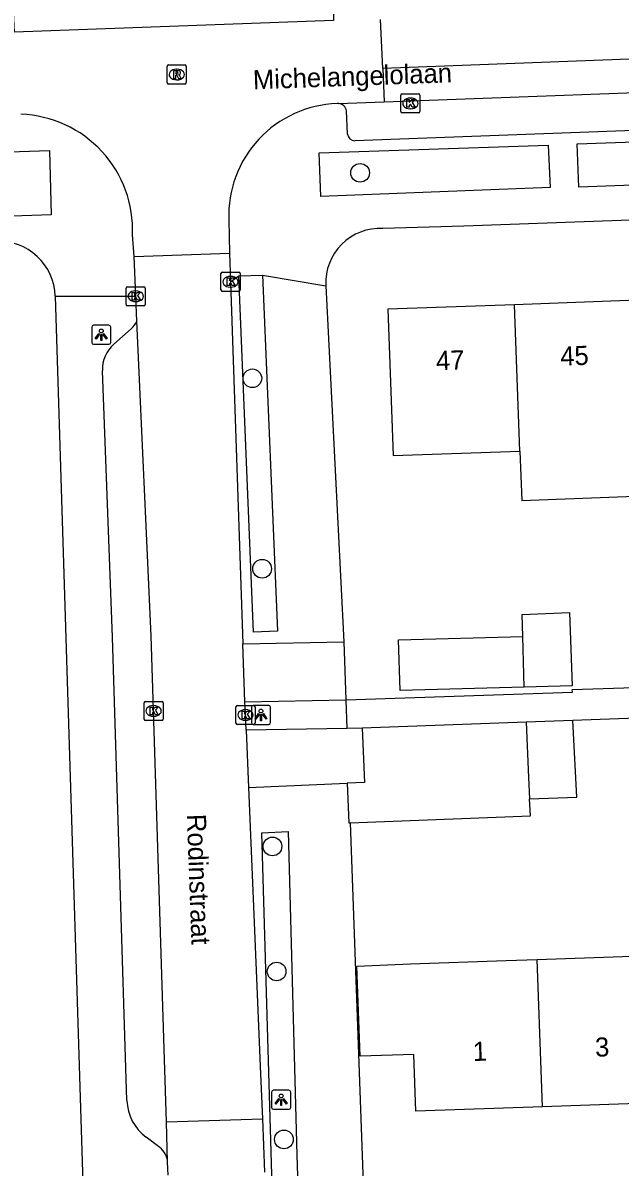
# Model space of a CAD drawing. Extents: x 160557 to 161245, y 385330 to 386505.
# Drawn here: x 160836.9 to 160868.1, y 386095.1 to 386154.9 of the extents above; entities that cross this region are included whole.
import ezdxf

# ---------------------------------------------------------------- set-up
doc = ezdxf.new("R2010")
doc.units = 0
for name, color, linetype in [('IMGEO_Boom', 7, 'Continuous'), ('IMGEO_Kolk', 7, 'Continuous'), ('IMGEO_Lichtpunt', 7, 'Continuous'), ('IMGEO_Openbare_ruimte_label', 7, 'Continuous'), ('IMGEO_Pand', 7, 'Continuous'), ('IMGEO_Pand_nummerreeks', 7, 'Continuous'), ('IMGEO_Rijbaan_lokaal_gesloten', 7, 'Continuous'), ('IMGEO_Rijbaan_lokaal_open', 7, 'Continuous'), ('IMGEO_Rioolput', 7, 'Continuous'), ('IMGEO_Voetpad_open', 7, 'Continuous')]:
    doc.layers.add(name, color=color, linetype=linetype)

msp = doc.modelspace()

# ---------------------------------------------------------------- linework, layer by layer
at = {"layer": 'IMGEO_Boom'}
for centre in [(160854.55, 386147.084), (160848.92, 386136.333), (160849.431, 386126.371), (160849.969, 386111.841), (160850.188, 386105.298), (160850.569, 386096.513)]:
    msp.add_circle(centre, 0.489, dxfattribs=at)
at = {"layer": 'IMGEO_Kolk'}
for p, q in [((160856.679, 386150.291), (160856.679, 386151.143)), ((160856.754, 386151.217), (160857.606, 386151.217)), ((160857.167, 386150.997), (160857.192, 386150.997)), ((160857.68, 386151.143), (160857.68, 386150.291)), ((160857.606, 386150.217), (160856.754, 386150.217)), ((160857.19, 386150.437), (160857.165, 386150.437)), ((160847.277, 386140.957), (160847.277, 386141.809)), ((160847.352, 386141.883), (160848.204, 386141.883)), ((160848.278, 386141.809), (160848.278, 386140.957)), ((160842.397, 386141.124), (160843.249, 386141.124)), ((160847.788, 386141.103), (160847.763, 386141.103)), ((160847.765, 386141.663), (160847.79, 386141.663)), ((160842.322, 386140.198), (160842.322, 386141.05)), ((160842.81, 386140.904), (160842.835, 386140.904)), ((160843.323, 386141.05), (160843.323, 386140.198)), ((160848.204, 386140.883), (160847.352, 386140.883)), ((160843.249, 386140.124), (160842.397, 386140.124)), ((160842.833, 386140.344), (160842.808, 386140.344)), ((160843.258, 386118.504), (160843.258, 386119.356)), ((160843.333, 386119.43), (160844.185, 386119.43)), ((160843.746, 386119.21), (160843.771, 386119.21)), ((160844.259, 386119.356), (160844.259, 386118.504)), ((160848.06, 386118.293), (160848.06, 386119.145)), ((160848.135, 386119.219), (160848.987, 386119.219)), ((160848.548, 386118.999), (160848.573, 386118.999)), ((160849.061, 386119.145), (160849.061, 386118.293)), ((160844.185, 386118.43), (160843.333, 386118.43)), ((160843.769, 386118.65), (160843.744, 386118.65)), ((160848.571, 386118.439), (160848.546, 386118.439)), ((160848.987, 386118.219), (160848.135, 386118.219))]:
    msp.add_line(p, q, dxfattribs=at)
for points in [[(160856.679, 386150.291), (160856.679, 386151.143)], [(160856.754, 386151.217), (160857.606, 386151.217)], [(160857, 386150.917), (160857.123, 386150.917), (160857.123, 386150.766), (160857.253, 386150.917), (160857.417, 386150.917), (160857.271, 386150.766), (160857.424, 386150.517), (160857.272, 386150.517), (160857.187, 386150.681), (160857.123, 386150.614), (160857.123, 386150.517), (160857, 386150.517), (160857, 386150.917)], [(160857.68, 386151.143), (160857.68, 386150.291)], [(160857.606, 386150.217), (160856.754, 386150.217)], [(160847.277, 386140.957), (160847.277, 386141.809)], [(160847.352, 386141.883), (160848.204, 386141.883)], [(160848.278, 386141.809), (160848.278, 386140.957)], [(160842.397, 386141.124), (160843.249, 386141.124)], [(160847.598, 386141.583), (160847.721, 386141.583), (160847.721, 386141.432), (160847.851, 386141.583), (160848.015, 386141.583), (160847.869, 386141.432), (160848.022, 386141.183), (160847.87, 386141.183), (160847.785, 386141.347), (160847.721, 386141.28), (160847.721, 386141.183), (160847.598, 386141.183), (160847.598, 386141.583)], [(160842.322, 386140.198), (160842.322, 386141.05)], [(160842.643, 386140.824), (160842.766, 386140.824), (160842.766, 386140.673), (160842.896, 386140.824), (160843.06, 386140.824), (160842.914, 386140.673), (160843.067, 386140.424), (160842.915, 386140.424), (160842.83, 386140.588), (160842.766, 386140.521), (160842.766, 386140.424), (160842.643, 386140.424), (160842.643, 386140.824)], [(160843.323, 386141.05), (160843.323, 386140.198)], [(160848.204, 386140.883), (160847.352, 386140.883)], [(160843.249, 386140.124), (160842.397, 386140.124)], [(160843.258, 386118.504), (160843.258, 386119.356)], [(160843.333, 386119.43), (160844.185, 386119.43)], [(160843.579, 386119.13), (160843.702, 386119.13), (160843.702, 386118.979), (160843.832, 386119.13), (160843.996, 386119.13), (160843.85, 386118.979), (160844.003, 386118.73), (160843.851, 386118.73), (160843.766, 386118.894), (160843.702, 386118.827), (160843.702, 386118.73), (160843.579, 386118.73), (160843.579, 386119.13)], [(160844.259, 386119.356), (160844.259, 386118.504)], [(160848.06, 386118.293), (160848.06, 386119.145)], [(160848.135, 386119.219), (160848.987, 386119.219)], [(160849.061, 386119.145), (160849.061, 386118.293)], [(160844.185, 386118.43), (160843.333, 386118.43)], [(160848.381, 386118.919), (160848.504, 386118.919), (160848.504, 386118.768), (160848.634, 386118.919), (160848.798, 386118.919), (160848.652, 386118.768), (160848.805, 386118.519), (160848.653, 386118.519), (160848.568, 386118.683), (160848.504, 386118.616), (160848.504, 386118.519), (160848.381, 386118.519), (160848.381, 386118.919)], [(160848.987, 386118.219), (160848.135, 386118.219)]]:
    msp.add_lwpolyline(points, dxfattribs=at)
for centre, start, end in [((160856.756, 386151.141), 91.55205, 178.44795), ((160856.756, 386151.141), 91.55205, 178.44795), ((160857.604, 386151.141), 1.55205, 88.44795), ((160857.604, 386151.141), 1.55205, 88.44795), ((160856.756, 386150.293), 181.55205, 268.44795), ((160856.756, 386150.293), 181.55205, 268.44795), ((160857.604, 386150.293), 271.55205, 358.44795), ((160857.604, 386150.293), 271.55205, 358.44795), ((160847.354, 386141.807), 91.55205, 178.44795), ((160847.354, 386141.807), 91.55205, 178.44795), ((160848.202, 386141.807), 1.55205, 88.44795), ((160848.202, 386141.807), 1.55205, 88.44795), ((160842.399, 386141.048), 91.55205, 178.44795), ((160842.399, 386141.048), 91.55205, 178.44795), ((160843.247, 386141.048), 1.55205, 88.44795), ((160843.247, 386141.048), 1.55205, 88.44795), ((160847.354, 386140.959), 181.55205, 268.44795), ((160847.354, 386140.959), 181.55205, 268.44795), ((160848.202, 386140.959), 271.55205, 358.44795), ((160848.202, 386140.959), 271.55205, 358.44795), ((160842.399, 386140.2), 181.55205, 268.44795), ((160842.399, 386140.2), 181.55205, 268.44795), ((160843.247, 386140.2), 271.55205, 358.44795), ((160843.247, 386140.2), 271.55205, 358.44795), ((160843.335, 386119.354), 91.55205, 178.44795), ((160843.335, 386119.354), 91.55205, 178.44795), ((160844.183, 386119.354), 1.55205, 88.44795), ((160844.183, 386119.354), 1.55205, 88.44795), ((160848.137, 386119.143), 91.55205, 178.44795), ((160848.137, 386119.143), 91.55205, 178.44795), ((160848.985, 386119.143), 1.55205, 88.44795), ((160848.985, 386119.143), 1.55205, 88.44795), ((160843.335, 386118.506), 181.55205, 268.44795), ((160843.335, 386118.506), 181.55205, 268.44795), ((160844.183, 386118.506), 271.55205, 358.44795), ((160844.183, 386118.506), 271.55205, 358.44795), ((160848.137, 386118.295), 181.55205, 268.44795), ((160848.137, 386118.295), 181.55205, 268.44795), ((160848.985, 386118.295), 271.55205, 358.44795), ((160848.985, 386118.295), 271.55205, 358.44795)]:
    msp.add_arc(centre, 0.0765, start, end, dxfattribs=at)
for centre, major_axis, ratio, start_param, end_param in [((160857.166, 386150.717), (-0.387, 0.002), 0.722429, 4.712389, 7.853982), ((160857.191, 386150.717), (-0.39, 0.002), 0.717154, 1.570796, 4.712389), ((160847.764, 386141.383), (-0.387, 0.002), 0.722429, 4.712389, 7.853982), ((160847.789, 386141.383), (-0.39, 0.002), 0.717154, 1.570796, 4.712389), ((160842.809, 386140.624), (-0.387, 0.002), 0.722429, 4.712389, 7.853982), ((160842.834, 386140.624), (-0.39, 0.002), 0.717154, 1.570796, 4.712389), ((160843.745, 386118.93), (-0.387, 0.002), 0.722429, 4.712389, 7.853982), ((160843.77, 386118.93), (-0.39, 0.002), 0.717154, 1.570796, 4.712389), ((160848.547, 386118.719), (-0.387, 0.002), 0.722429, 4.712389, 7.853982), ((160848.572, 386118.719), (-0.39, 0.002), 0.717154, 1.570796, 4.712389)]:
    msp.add_ellipse(centre, major_axis=major_axis, ratio=ratio, start_param=start_param, end_param=end_param, dxfattribs=at)
at = {"layer": 'IMGEO_Lichtpunt'}
for p, q in [((160840.524, 386139.014), (160840.524, 386138.207)), ((160840.524, 386139.014), (160840.524, 386138.207)), ((160841.426, 386139.109), (160840.618, 386139.109)), ((160841.426, 386139.109), (160840.618, 386139.109)), ((160841.52, 386138.207), (160841.52, 386139.014)), ((160841.52, 386138.207), (160841.52, 386139.014)), ((160840.618, 386138.113), (160841.426, 386138.113)), ((160840.618, 386138.113), (160841.426, 386138.113)), ((160848.871, 386119.125), (160848.871, 386118.318)), ((160848.871, 386119.125), (160848.871, 386118.318)), ((160849.773, 386119.22), (160848.965, 386119.22)), ((160849.773, 386119.22), (160848.965, 386119.22)), ((160849.867, 386118.318), (160849.867, 386119.125)), ((160849.867, 386118.318), (160849.867, 386119.125)), ((160848.965, 386118.224), (160849.773, 386118.224)), ((160848.965, 386118.224), (160849.773, 386118.224)), ((160849.928, 386098.99), (160849.928, 386098.183)), ((160849.928, 386098.99), (160849.928, 386098.183)), ((160850.83, 386099.085), (160850.022, 386099.085)), ((160850.83, 386099.085), (160850.022, 386099.085)), ((160850.924, 386098.183), (160850.924, 386098.99)), ((160850.924, 386098.183), (160850.924, 386098.99)), ((160850.022, 386098.089), (160850.83, 386098.089)), ((160850.022, 386098.089), (160850.83, 386098.089))]:
    msp.add_line(p, q, dxfattribs=at)
for points in [[(160840.898, 386138.678), (160840.937, 386138.65), (160840.749, 386138.388), (160840.711, 386138.415), (160840.898, 386138.678)], [(160841, 386138.63), (160841.047, 386138.63), (160841.047, 386138.308), (160841, 386138.308), (160841, 386138.63)], [(160841.11, 386138.65), (160841.148, 386138.677), (160841.335, 386138.415), (160841.296, 386138.387), (160841.11, 386138.65)], [(160849.245, 386118.789), (160849.284, 386118.761), (160849.096, 386118.499), (160849.058, 386118.526), (160849.245, 386118.789)], [(160849.347, 386118.741), (160849.394, 386118.741), (160849.394, 386118.419), (160849.347, 386118.419), (160849.347, 386118.741)], [(160849.457, 386118.761), (160849.495, 386118.788), (160849.682, 386118.526), (160849.643, 386118.498), (160849.457, 386118.761)], [(160850.302, 386098.654), (160850.341, 386098.626), (160850.153, 386098.364), (160850.115, 386098.391), (160850.302, 386098.654)], [(160850.404, 386098.606), (160850.451, 386098.606), (160850.451, 386098.284), (160850.404, 386098.284), (160850.404, 386098.606)], [(160850.514, 386098.626), (160850.552, 386098.653), (160850.739, 386098.391), (160850.7, 386098.363), (160850.514, 386098.626)]]:
    msp.add_lwpolyline(points, dxfattribs=at)
for centre in [(160841.023, 386138.812), (160849.37, 386118.923), (160850.427, 386098.788)]:
    msp.add_circle(centre, 0.0994, dxfattribs=at)
for centre, start, end in [((160840.618, 386139.014), 90, 180), ((160840.618, 386139.014), 90, 180), ((160841.426, 386139.014), 0, 90), ((160841.426, 386139.014), 0, 90), ((160840.618, 386138.207), 180, 270), ((160840.618, 386138.207), 180, 270), ((160841.426, 386138.207), 270, 0), ((160841.426, 386138.207), 270, 360), ((160848.965, 386119.125), 90, 180), ((160848.965, 386119.125), 90, 180), ((160849.773, 386119.125), 0, 90), ((160849.773, 386119.125), 0, 90), ((160848.965, 386118.318), 180, 270), ((160848.965, 386118.318), 180, 270), ((160849.773, 386118.318), 270, 0), ((160849.773, 386118.318), 270, 360), ((160850.022, 386098.99), 90, 180), ((160850.022, 386098.99), 90, 180), ((160850.83, 386098.99), 0, 90), ((160850.83, 386098.99), 0, 90), ((160850.022, 386098.183), 180, 270), ((160850.022, 386098.183), 180, 270), ((160850.83, 386098.183), 270, 0), ((160850.83, 386098.183), 270, 360)]:
    msp.add_arc(centre, 0.0946, start, end, dxfattribs=at)
at = {"layer": 'IMGEO_Pand'}
for points in [[(160862.627, 386140.185), (160855.997, 386139.944), (160856.275, 386132.287), (160862.905, 386132.528)], [(160869.024, 386140.417), (160862.627, 386140.185)], [(160862.905, 386132.528), (160862.627, 386140.185)], [(160862.905, 386132.528), (160862.998, 386129.949), (160867.995, 386130.13), (160869.393, 386130.181)], [(160863.059, 386122.828), (160863.025, 386123.974), (160865.488, 386124.085), (160865.632, 386120.252), (160863.133, 386120.182)], [(160863.133, 386120.182), (160856.64, 386120), (160856.565, 386122.646), (160863.059, 386122.828)], [(160863.133, 386120.182), (160863.059, 386122.828)], [(160863.226, 386118.34), (160854.652, 386118.021)], [(160865.674, 386118.431), (160863.226, 386118.34)], [(160863.226, 386118.34), (160863.357, 386115.45), (160863.408, 386114.33)], [(160863.408, 386114.33), (160865.871, 386114.418), (160865.674, 386118.431)], [(160854.652, 386118.021), (160854.781, 386115.184), (160853.873, 386115.156)], [(160853.873, 386115.156), (160853.967, 386113.081), (160854.031, 386113.083)], [(160854.031, 386113.083), (160863.448, 386113.434), (160863.408, 386114.33)], [(160864.075, 386098.217), (160857.455, 386097.984), (160857.35, 386100.963), (160854.553, 386100.865), (160854.384, 386105.575), (160857.184, 386105.692), (160862.181, 386105.868), (160863.804, 386105.925)], [(160863.804, 386105.925), (160870.25, 386106.152)], [(160864.075, 386098.217), (160863.804, 386105.925)], [(160870.521, 386098.444), (160864.075, 386098.217)]]:
    msp.add_lwpolyline(points, dxfattribs=at)
at = {"layer": 'IMGEO_Rijbaan_lokaal_gesloten'}
for points in [[(161019.987, 386158.535), (160930.562, 386155.29), (160886.579, 386153.705), (160855.734, 386152.543)], [(160853.165, 386156.751), (160853.168, 386155.053), (160836.492, 386154.451), (160836.399, 386156.169)], [(160855.809, 386150.8), (160895.292, 386152.266)]]:
    msp.add_lwpolyline(points, dxfattribs=at)
at = {"layer": 'IMGEO_Rijbaan_lokaal_open'}
for points in [[(160855.734, 386152.543), (160855.623, 386155.101)], [(160855.734, 386152.543), (160855.809, 386150.8)], [(160853.417, 386150.711), (160853.345, 386150.708)], [(160853.417, 386150.711), (160855.809, 386150.8)], [(160847.687, 386144.624), (160847.727, 386142.88)], [(160842.745, 386142.706), (160842.655, 386143.834)], [(160842.745, 386142.706), (160847.727, 386142.88)], [(160847.727, 386142.88), (160847.778, 386141.383)], [(160842.823, 386140.624), (160842.745, 386142.706)], [(160847.778, 386141.383), (160848.42, 386122.44)], [(160842.882, 386139.328), (160842.823, 386140.624)], [(160844.426, 386097.434), (160844.331, 386100.693), (160843.637, 386122.858), (160842.882, 386139.328)], [(160848.534, 386119.412), (160848.42, 386122.44)], [(160848.595, 386117.919), (160848.544, 386119.133), (160848.534, 386119.412)], [(160848.595, 386117.919), (160848.721, 386114.928)], [(160848.721, 386114.928), (160849.35, 386099.937), (160849.447, 386097.589)], [(160844.426, 386097.434), (160849.447, 386097.589)], [(160844.491, 386095.326), (160844.426, 386097.434)], [(160849.447, 386097.589), (160849.562, 386094.801)], [(160844.511, 386094.645), (160844.491, 386095.326)]]:
    msp.add_lwpolyline(points, dxfattribs=at)
for centre, radius, start, end in [((160853.554, 386144.841), 5.871, 92.03882, 182.11674), ((160836.61, 386144.099), 6.05, 357.48737, 87.98567)]:
    msp.add_arc(centre, radius, start, end, dxfattribs=at)
at = {"layer": 'IMGEO_Rioolput'}
for p, q in [((160844.467, 386151.802), (160844.467, 386152.654)), ((160844.542, 386152.728), (160845.394, 386152.728)), ((160844.955, 386152.508), (160844.98, 386152.508)), ((160845.468, 386152.654), (160845.468, 386151.802)), ((160844.978, 386151.948), (160844.953, 386151.948)), ((160845.394, 386151.728), (160844.542, 386151.728))]:
    msp.add_line(p, q, dxfattribs=at)
for points in [[(160844.467, 386151.802), (160844.467, 386152.654)], [(160844.542, 386152.728), (160845.394, 386152.728)], [(160845.468, 386152.654), (160845.468, 386151.802)], [(160845.056, 386152.426), (160844.804, 386152.428), (160844.804, 386152.028)], [(160844.804, 386152.028), (160844.928, 386152.028), (160844.928, 386152.19), (160844.939, 386152.19)], [(160844.982, 386152.347), (160844.928, 386152.347), (160844.928, 386152.266)], [(160844.928, 386152.266), (160844.98, 386152.266)], [(160844.986, 386152.161), (160845.057, 386152.028), (160845.197, 386152.028), (160845.132, 386152.154)], [(160845.394, 386151.728), (160844.542, 386151.728)]]:
    msp.add_lwpolyline(points, dxfattribs=at)
for centre, radius, start, end in [((160844.544, 386152.652), 0.0765, 91.55205, 178.44795), ((160844.544, 386152.652), 0.0765, 91.55205, 178.44795), ((160845.392, 386152.652), 0.0765, 1.55205, 88.44795), ((160845.392, 386152.652), 0.0765, 1.55205, 88.44795), ((160844.938, 386152.137), 0.0533, 26.02933, 88.69889), ((160844.964, 386152.455), 0.19, 274.7715, 282.96867), ((160844.988, 386152.251), 0.0964, 77.00612, 93.18647), ((160845.002, 386152.308), 0.0378, 276.66336, 79.67722), ((160845.055, 386152.316), 0.109, 350.36119, 89.41601), ((160845.053, 386152.316), 0.112, 277.58423, 350.98172), ((160845.037, 386152.101), 0.108, 29.51342, 73.79051), ((160844.544, 386151.804), 0.0765, 181.55205, 268.44795), ((160844.544, 386151.804), 0.0765, 181.55205, 268.44795), ((160845.392, 386151.804), 0.0765, 271.55205, 358.44795), ((160845.392, 386151.804), 0.0765, 271.55205, 358.44795)]:
    msp.add_arc(centre, radius, start, end, dxfattribs=at)
for centre, major_axis, ratio, start_param, end_param in [((160844.954, 386152.228), (-0.387, 0.002), 0.722429, 4.712389, 7.853982), ((160844.979, 386152.228), (-0.39, 0.002), 0.717154, 1.570796, 4.712389)]:
    msp.add_ellipse(centre, major_axis=major_axis, ratio=ratio, start_param=start_param, end_param=end_param, dxfattribs=at)
at = {"layer": 'IMGEO_Voetpad_open'}
for points in [[(160853.899, 386149.112), (160853.837, 386150.328)], [(160894.735, 386150.26), (160854.268, 386148.757)], [(160882.464, 386146.944), (160865.987, 386146.341), (160865.903, 386148.598), (160882.403, 386149.179), (160882.464, 386146.944)], [(160864.478, 386146.314), (160852.491, 386145.852), (160852.41, 386148.13), (160864.382, 386148.531), (160864.478, 386146.314)], [(160818.902, 386147.546), (160828.903, 386147.908), (160828.985, 386146.077), (160834.678, 386146.325), (160834.627, 386148.123), (160838.311, 386148.245), (160838.408, 386144.89), (160819.026, 386144.22), (160818.902, 386147.546)], [(160894.793, 386145.542), (160859.966, 386144.293), (160855.735, 386144.169)], [(160847.778, 386141.383), (160848.216, 386141.688)], [(160848.216, 386141.688), (160849.446, 386141.735)], [(160849.446, 386141.735), (160850.227, 386123.104), (160848.973, 386123.051), (160848.216, 386141.688)], [(160849.446, 386141.735), (160852.76, 386141.165)], [(160852.758, 386141.207), (160852.76, 386141.165)], [(160852.76, 386141.165), (160853.706, 386122.542)], [(160838.619, 386140.638), (160842.823, 386140.624)], [(160838.619, 386140.638), (160840.051, 386094.232)], [(160841.675, 386138.115), (160842.588, 386138.915)], [(160842.362, 386098.555), (160841.605, 386122.788), (160841.08, 386136.733)], [(160848.42, 386122.44), (160853.706, 386122.542)], [(160853.706, 386122.542), (160853.806, 386119.514)], [(160853.806, 386119.514), (160865.645, 386119.916), (160865.64, 386120.051), (160873.709, 386120.321)], [(160848.534, 386119.412), (160853.806, 386119.514)], [(160853.806, 386119.514), (160853.856, 386118.02)], [(160873.8, 386118.733), (160865.674, 386118.431)], [(160853.856, 386118.02), (160848.595, 386117.919)], [(160854.652, 386118.021), (160853.856, 386118.02)], [(160848.721, 386114.928), (160853.873, 386115.156)], [(160854.031, 386113.083), (160854.735, 386093.738)], [(160851.247, 386095.686), (160851.311, 386093.515), (160850.472, 386093.49), (160849.975, 386093.475), (160849.409, 386112.559), (160850.792, 386112.617), (160851.247, 386095.686)], [(160844.087, 386096.095), (160843.373, 386096.625)]]:
    msp.add_lwpolyline(points, dxfattribs=at)
for centre, radius, start, end in [((160853.397, 386150.267), 0.444, 7.88998, 87.38635), ((160854.283, 386149.141), 0.385, 184.38046, 267.83512), ((160855.588, 386141.339), 2.834, 87.03578, 182.6748), ((160835.652, 386140.539), 2.969, 1.90591, 92.10238), ((160841.72, 386139.844), 1.272, 313.05737, 336.0512), ((160842.835, 386136.797), 1.756, 131.33873, 182.07409), ((160844.859, 386098.633), 2.498, 181.79367, 233.5005), ((160843.393, 386095.24), 1.102, 4.4949, 50.93616)]:
    msp.add_arc(centre, radius, start, end, dxfattribs=at)

# ---------------------------------------------------------------- texts
at = {"layer": 'IMGEO_Openbare_ruimte_label'}
for s, rotation, p in [('Michelangelolaan', 2.06382, (160848.966, 386151.45)), ('Rodinstraat', 272.06382, (160845.494, 386113.522))]:
    msp.add_text(s, height=1, rotation=rotation, dxfattribs=at).set_placement(p)
at = {"layer": 'IMGEO_Pand_nummerreeks'}
for s, rotation, p in [('47', 2.07984, (160858.536, 386136.755)), ('45', 2.07984, (160865.027, 386136.99)), ('1', 2.01488, (160860.457, 386100.611)), ('3', 2.01488, (160866.848, 386100.835))]:
    msp.add_text(s, height=1, rotation=rotation, dxfattribs=at).set_placement(p)

doc.saveas('drawing.dxf')
